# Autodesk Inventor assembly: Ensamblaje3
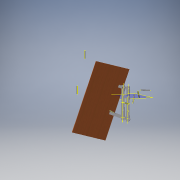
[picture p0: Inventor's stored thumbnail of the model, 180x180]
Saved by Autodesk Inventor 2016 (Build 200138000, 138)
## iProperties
Created: 2016-06
Part Number: Ensamblaje3
Material: Genérico
Document SubType Name: Assembly
Designer: adm
Author: adm
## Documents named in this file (7)
- C:\Users\adm\Desktop\proyecto del profe. valcarcel\trabajo3\Ensamblaje3.iam
- C:\Users\adm\Desktop\proyecto del profe. valcarcel\trabajo3\tablero.ipt
- C:\Users\adm\Desktop\proyecto del profe. valcarcel\trabajo3\soporte 2a.ipt
- C:\Users\adm\Desktop\proyecto del profe. valcarcel\trabajo3\eje.ipt
- C:\Users\adm\Desktop\proyecto del profe. valcarcel\trabajo3\soporte1a.ipt
- C:\Users\adm\Desktop\proyecto del profe. valcarcel\trabajo3\tabla de union de ejes.ipt
- C:\Users\adm\Desktop\proyecto del profe. valcarcel\trabajo3\159.iam
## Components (18 placed, 6 different names)
1. tablero:1 — Coincidencia:3, Nivelación:4, Coincidencia:6, Nivelación:9, Coincidencia:16, Coincidencia:17
2. soporte 2a:1 — Coincidencia:1, Coincidencia:2, Nivelación:1, Nivelación:2, Nivelación:3, Insertar:1, Coincidencia:3, Nivelación:4, Tangente:2, Coincidencia:28, Insertar:5
3. soporte 2a:2 — Coincidencia:1, Coincidencia:2, Nivelación:1, Nivelación:2, Nivelación:3, Insertar:1, Nivelación:8, Tangente:1
4. soporte 2a:3 — Coincidencia:6, Coincidencia:29
5. soporte 2a:4 — Nivelación:8, Coincidencia:30
6. eje:1 — Coincidencia:7, Coincidencia:8, Coincidencia:9
7. eje:2 — Coincidencia:7, Coincidencia:8, Coincidencia:9, Tangente:1, Tangente:2
8. soporte1a:1 — Coincidencia:17, Nivelación:10, Tangente:3, Insertar:3
9. soporte1a:2 — Nivelación:9, Coincidencia:16, Nivelación:10, Coincidencia:31, Insertar:4
10. eje:3
11. eje:4 — Tangente:3
12. tabla de union de ejes:1 — Coincidencia:28, Coincidencia:31, Insertar:4, Insertar:5, Coincidencia:32, Nivelación:11, Coincidencia:33, Nivelación:12, Nivelación:13
13. tabla de union de ejes:2 — Coincidencia:29, Insertar:3, Coincidencia:30
14. 159:1 [sub-assembly] — Coincidencia:32, Nivelación:11, Coincidencia:33
15. 159:2 [sub-assembly]
16. 159:3 [sub-assembly] — Coincidencia:34
17. 159:4 [sub-assembly]
18. 159:5 [sub-assembly]
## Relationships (33: Mate 16, Flush 10, Insert 4, Tangent 3)
- Coincidencia:1 [Mate]: soporte 2a:1 ↔ soporte 2a:2
- Coincidencia:2 [Mate]: soporte 2a:1 ↔ soporte 2a:2
- Nivelación:1 [Flush]: soporte 2a:1 ↔ soporte 2a:2
- Nivelación:2 [Flush]: soporte 2a:1 ↔ soporte 2a:2
- Nivelación:3 [Flush]: soporte 2a:1 ↔ soporte 2a:2
- Insertar:1: soporte 2a:1 ↔ soporte 2a:2
- Coincidencia:3 [Mate]: tablero:1 ↔ soporte 2a:1
- Nivelación:4 [Flush]: tablero:1 ↔ soporte 2a:1
- Coincidencia:6 [Mate]: tablero:1 ↔ soporte 2a:3
- Nivelación:8 [Flush]: soporte 2a:2 ↔ soporte 2a:4
- Coincidencia:7 [Mate]: eje:1 ↔ eje:2
- Coincidencia:8 [Mate]: eje:1 ↔ eje:2
- Coincidencia:9 [Mate]: eje:1 ↔ eje:2
- Tangente:1: soporte 2a:2 ↔ eje:2
- Tangente:2: soporte 2a:1 ↔ eje:2
- Nivelación:9 [Flush]: tablero:1 ↔ soporte1a:2
- Coincidencia:16 [Mate]: tablero:1 ↔ soporte1a:2
- Coincidencia:17 [Mate]: tablero:1 ↔ soporte1a:1
- Nivelación:10 [Flush]: soporte1a:1 ↔ soporte1a:2
- Tangente:3: soporte1a:1 ↔ eje:4
- Coincidencia:28 [Mate]: soporte 2a:1 ↔ tabla de union de ejes:1
- Coincidencia:29 [Mate]: soporte 2a:3 ↔ tabla de union de ejes:2
- Insertar:3: soporte1a:1 ↔ tabla de union de ejes:2
- Coincidencia:30 [Mate]: soporte 2a:4 ↔ tabla de union de ejes:2
- Coincidencia:31 [Mate]: soporte1a:2 ↔ tabla de union de ejes:1
- Insertar:4: soporte1a:2 ↔ tabla de union de ejes:1
- Insertar:5: soporte 2a:1 ↔ tabla de union de ejes:1
- Coincidencia:32 [Mate]: tabla de union de ejes:1 ↔ 159:1
- Nivelación:11 [Flush]: tabla de union de ejes:1 ↔ 159:1
- Coincidencia:33 [Mate]: tabla de union de ejes:1 ↔ 159:1
- Nivelación:12 [Flush]: tabla de union de ejes:1
- Coincidencia:34 [Mate]: 159:3
- Nivelación:13 [Flush]: tabla de union de ejes:1
## Named parameters: d8_d0 = 0, d9_d1 = 0, d10_d2 = 0, d11_d3 = 0, d12_d4 = 0, d13_d5 = 0
